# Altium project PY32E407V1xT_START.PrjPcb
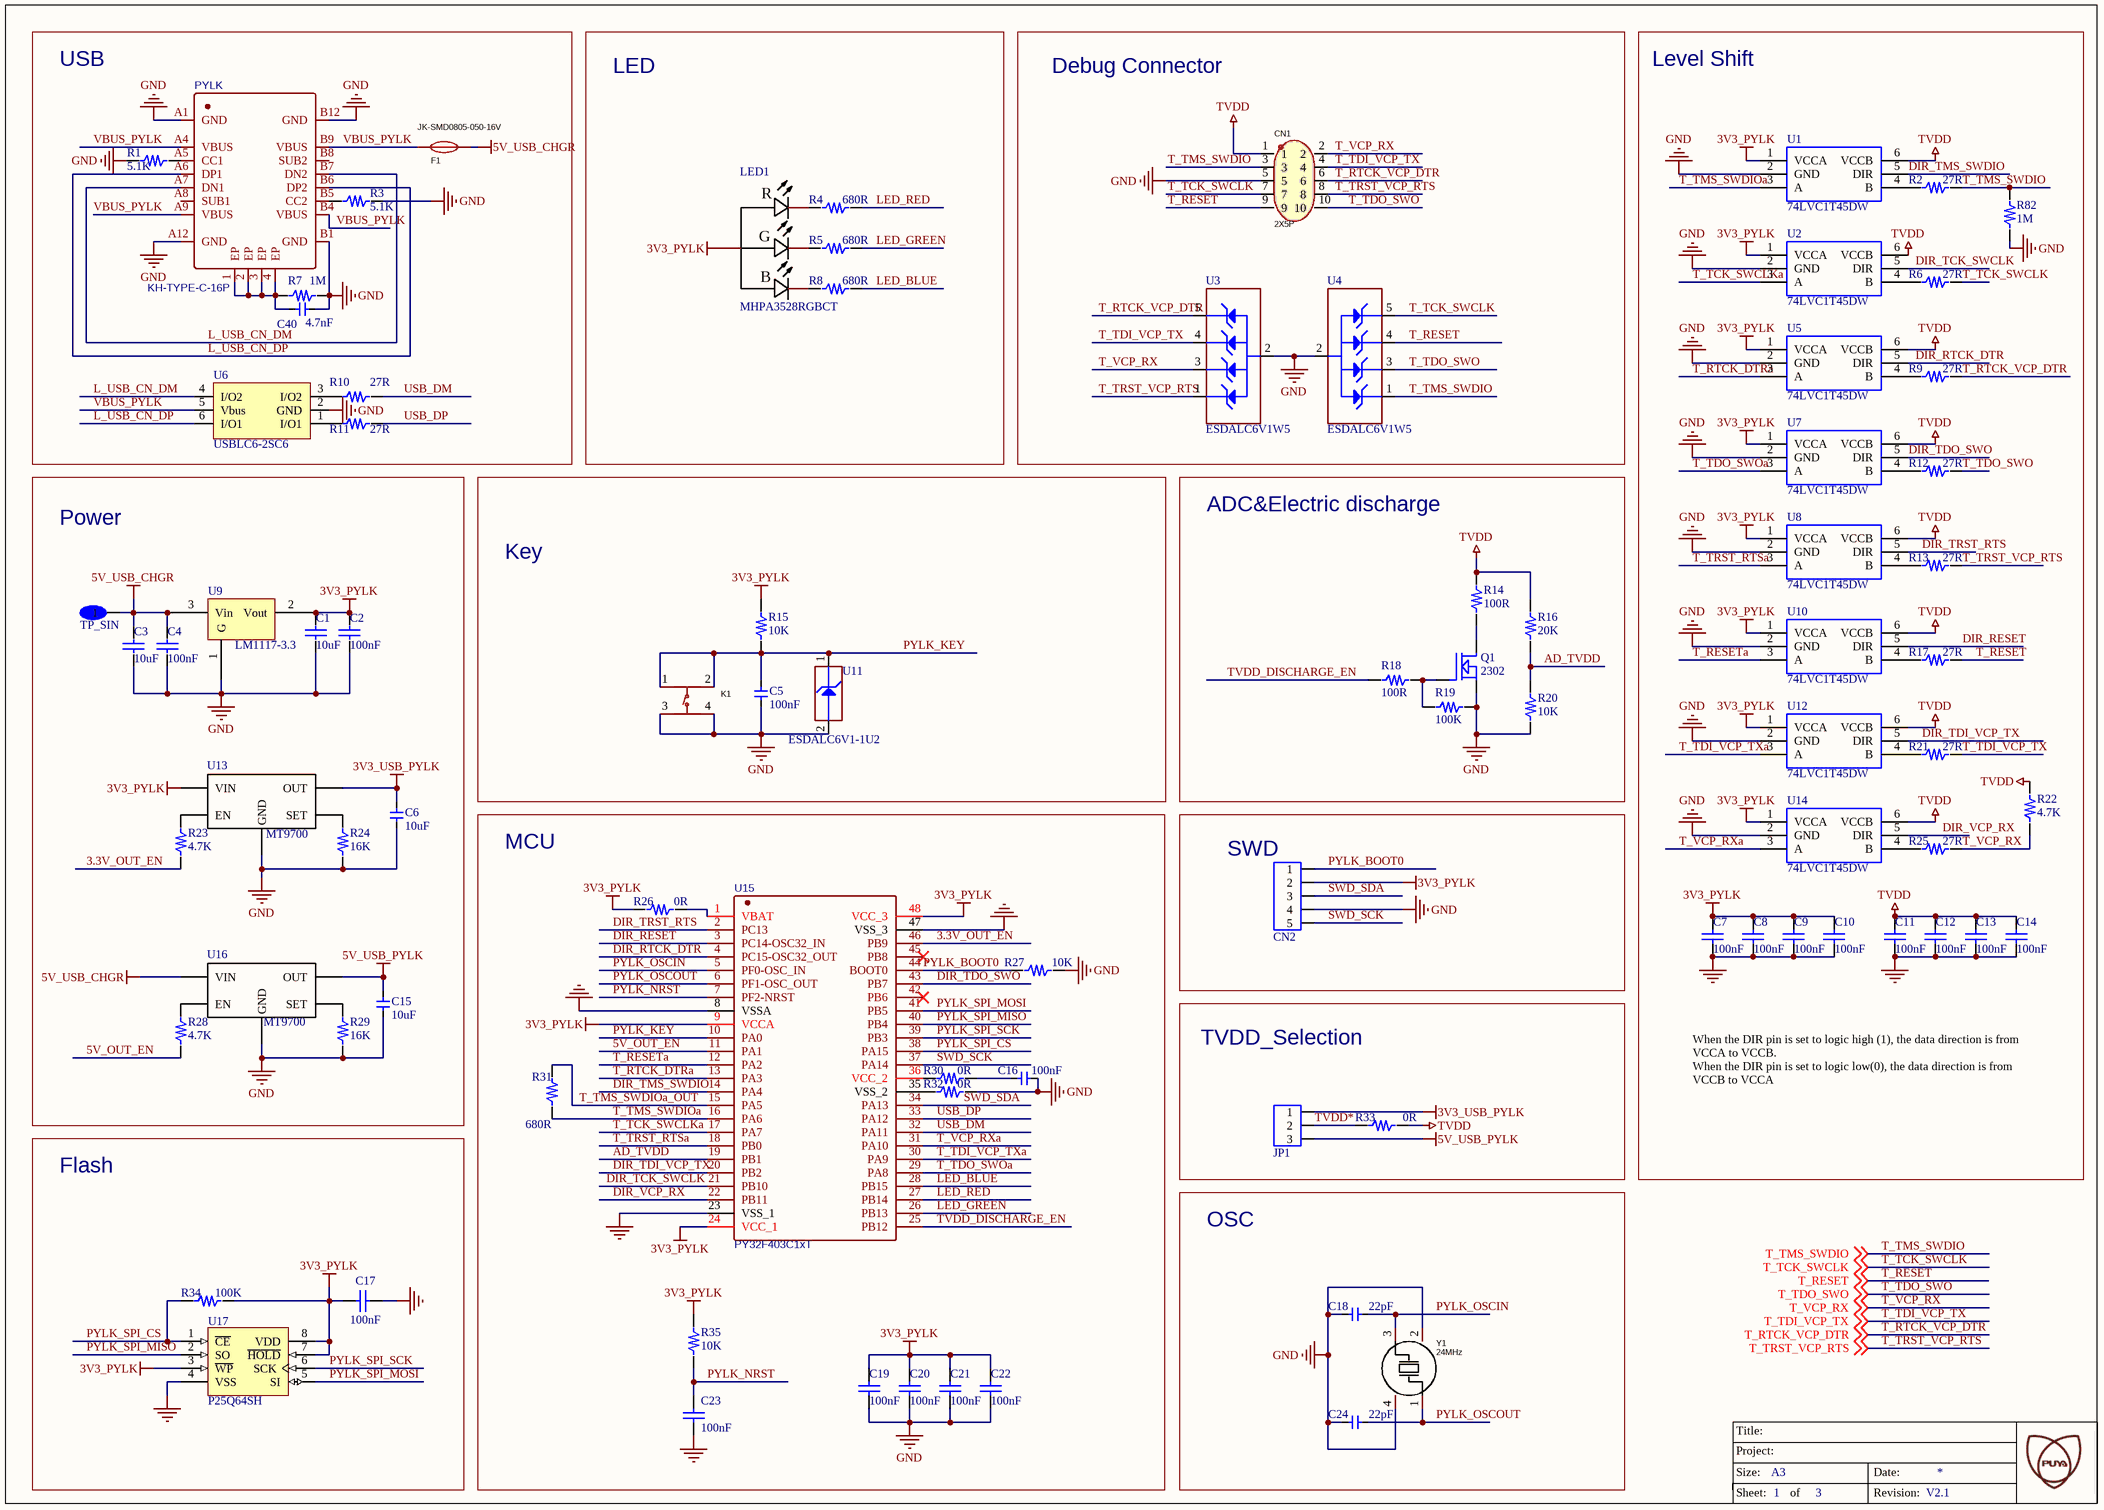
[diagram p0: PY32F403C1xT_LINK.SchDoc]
3 sheets, 210 parts. Net scope: global (net labels, ports and power ports of the same name join across sheets).
Board file: PY32E407V1xT_START.PcbDoc
Sheets:
  PY32F403C1xT_LINK.SchDoc
  PY32E407V1xT_START.SchDoc
  PY32E407V1xT_USB.SchDoc

## Sheet PY32F403C1xT_LINK.SchDoc: =DocumentName
size A3; Revision: V2.1; SheetNumber: 1; SheetTotal: 3; Project: PY32E407V1xT_START.PrjPcb

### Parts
5V_USB_CHGR  TP_SIN  [TP_SIN]
C1  10uF  [C0805]
C2  100nF  [C0603]
C3  10uF  [C0805]
C4  100nF  [C0603]
C5  100nF  [C0603]
C6  10uF  [C0805]
C7  100nF  [C0603]
C8  100nF  [C0603]
C9  100nF  [C0603]
C10  100nF  [C0603]
C11  100nF  [C0603]
C12  100nF  [C0603]
C13  100nF  [C0603]
C14  100nF  [C0603]
C15  10uF  [C0805]
C16  100nF  [C0603]
C17  100nF  [C0603]
C18  22pF  [C0603]
C19  100nF  [C0603]
C20  100nF  [C0603]
C21  100nF  [C0603]
C22  100nF  [C0603]
C23  100nF  [C0603]
C24  22pF  [C0603]
C40  4.7nF  [C0603]
CN1  2X5P  [HDR2X5]
CN2  CON5  [CON5]  (value not drawn)
F1  JK-SMD0805-050-16V  [F0805]
JP1  CON3  [CON3]  (value not drawn)
K1  TS-KG02S  [Switch]  (value not drawn)
LED1  MHPA3528RGBCT  [LED-ARRAY-SMD_4P-L3.5-W2.8-TL]
PYLK  KH-TYPE-C-16P  [USB-C-SMD_KH-TYPE-C-16P]
Q1  2302  [SOT23]
R1  5.1K  [R0603]
R2  27R  [R0603]
R3  5.1K  [R0603]
R4  680R  [R0603]
R5  680R  [R0603]
R6  27R  [R0603]
R7  1M  [R0603]
R8  680R  [R0603]
R9  27R  [R0603]
R10  27R  [R0603]
R11  27R  [R0603]
R12  27R  [R0603]
R13  27R  [R0603]
R14  100R  [R0805]
R15  10K  [R0603]
R16  20K  [R0603]
R17  27R  [R0603]
R18  100R  [R0603]
R19  100K  [R0603]
R20  10K  [R0603]
R21  27R  [R0603]
R22  4.7K  [R0603]
R23  4.7K  [R0603]
R24  16K  [R0603]
R25  27R  [R0603]
R26  0R  [JP2_SMD]
R27  10K  [R0603]
R28  4.7K  [R0603]
R29  16K  [R0603]
R30  0R  [JP2_SMD]
R31  680R  [R0603]
R32  0R  [JP2_SMD]
R33  0R  [JP2_SMD]
R34  100K  [R0603]
R35  10K  [R0603]
R82  1M  [R0603]
U1  74LVC1T45DW  [SOT363]
U2  74LVC1T45DW  [SOT363]
U3  value ESDALC6V1W5  [ESD_SOT323-5L]  (hidden comment: ESD_6V1)
U4  value ESDALC6V1W5  [ESD_SOT323-5L]  (hidden comment: ESD_6V1)
U5  74LVC1T45DW  [SOT363]
U6  USBLC6-2SC6  [SOT23-6]
U7  74LVC1T45DW  [SOT363]
U8  74LVC1T45DW  [SOT363]
U9  LM1117-3.3  [LM1117-3.3]
U10  74LVC1T45DW  [SOT363]
U11  value ESDALC6V1-1U2  [ESD_ST0201]  (hidden comment: ESD-TRANSIL)
U12  74LVC1T45DW  [SOT363]
U13  MT9700  [SOT23-5]
U14  74LVC1T45DW  [SOT363]
U15  PY32F403C1xT  [LQFP-48_L7.0-W7.0-P0.50-LS9.0-BL]
U16  MT9700  [SOT23-5]
U17  P25Q64SH  [SOP-8P]
Y1  24MHz  [CRYSTAL-SMD_4P-L3.2-W2.5-BL]

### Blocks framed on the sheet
USB: C40 F1 PYLK R1 R3 R7 R10 R11 U6
LED: LED1 R4 R5 R8
Debug Connector: CN1 U3 U4
Level Shift: C7-C14 R2 R6 R9 R12 R13 R17 R21 R22 R25 R82 U1 U2 U5 U7 U8 U10 U12 U14
Power: 5V_USB_CHGR C1-C4 C6 C15 R23 R24 R28 R29 U9 U13 U16
Key: C5 K1 R15 U11
ADC&Electric discharge: Q1 R14 R16 R18-R20
MCU: C16 C19-C23 R26 R27 R30-R32 R35 U15
SWD: CN2
TVDD_Selection: JP1 R33
Flash: C17 R34 U17
OSC: C18 C24 Y1

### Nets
3V3_PYLK: C1.2 C2.2 C7.2 C8.2 C9.2 C10.2 C17.2 C19.2 C20.2 C21.2 C22.2 CN2.2 LED1.1(-) R15.2 R26.1 R34.2 R35.2 U1.1(VCCA) U2.1(VCCA) U5.1(VCCA) U7.1(VCCA) U8.1(VCCA) U9.2(Vout) U10.1(VCCA) U12.1(VCCA) U13.5(VIN) U14.1(VCCA) U15.9(VCCA) U15.24(VCC_1) U15.48(VCC_3) U17.3(~{WP}) U17.7(~{HOLD}) U17.8(VDD)
3V3_USB_PYLK: C6.2 JP1.1 U13.1(OUT)
5V_USB_CHGR: 5V_USB_CHGR.1 C3.2 C4.2 F1.2 U9.3(Vin) U16.5(VIN)
5V_USB_PYLK: C15.2 JP1.3 U16.1(OUT)
GND: C1.1 C2.1 C3.1 C4.1 C5.1 C6.1 C7.1 C8.1 C9.1 C10.1 C11.1 C12.1 C13.1 C14.1 C15.1 C16.1 C17.1 C18.1 C19.1 C20.1 C21.1 C22.1 C23.1 C24.1 C40.1 CN1.5 CN2.4 K1.3 K1.4 PYLK.A1(GND) PYLK.A12(GND) PYLK.B1(GND) PYLK.B12(GND) Q1.2(S) R1.1 R3.2 R7.2 R19.1 R20.1 R24.1 R27.2 R29.1 R32.2 R82.1 U1.2(GND) U2.2(GND) U3.2(GND) U4.2(GND) U5.2(GND) U6.2(GND) U7.2(GND) U8.2(GND) U9.1(G) U10.2(GND) U11.2(GND) U12.2(GND) U13.2(GND) U14.2(GND) U15.8(VSSA) U15.23(VSS_1) U15.47(VSS_3) U16.2(GND) U17.4(VSS) Y1.2(GND) Y1.4(GND)
TVDD: C11.2 C12.2 C13.2 C14.2 CN1.1 R14.2 R16.2 R22.2 R33.2 U1.6(VCCB) U2.6(VCCB) U5.6(VCCB) U7.6(VCCB) U8.6(VCCB) U10.6(VCCB) U12.6(VCCB) U14.6(VCCB)
3.3V_OUT_EN: R23.1 U15.46(PB9)
5V_OUT_EN: R28.1 U15.11(PA1)
AD_TVDD: R16.1 R20.2 U15.19(PB1)
DIR_RESET: U10.5(DIR) U15.3(PC14-OSC32_IN)
DIR_RTCK_DTR: U5.5(DIR) U15.4(PC15-OSC32_OUT)
DIR_TCK_SWCLK: U2.5(DIR) U15.21(PB10)
DIR_TDI_VCP_TX: U12.5(DIR) U15.20(PB2)
DIR_TDO_SWO: U7.5(DIR) U15.43(PB7)
DIR_TMS_SWDIO: U1.5(DIR) U15.14(PA4)
DIR_TRST_RTS: U8.5(DIR) U15.2(PC13)
DIR_VCP_RX: U14.5(DIR) U15.22(PB11)
L_USB_CN_DM: PYLK.A7(DN1) PYLK.B7(DN2) U6.4(I/O2)
L_USB_CN_DP: PYLK.A6(DP1) PYLK.B6(DP2) U6.6(I/O1)
LED_BLUE: R8.2 U15.28(PB15)
LED_GREEN: R5.2 U15.26(PB13)
LED_RED: R4.2 U15.27(PB14)
PYLK_BOOT0: CN2.1 R27.1 U15.44(BOOT0)
PYLK_KEY: C5.2 K1.1 K1.2 R15.1 U11.1(IO1) U15.10(PA0)
PYLK_NRST: C23.2 R35.1 U15.7(PF2-NRST)
PYLK_OSCIN: C18.2 U15.5(PF0-OSC_IN) Y1.3(OSC2)
PYLK_OSCOUT: C24.2 U15.6(PF1-OSC_OUT) Y1.1(OSC1)
PYLK_SPI_CS: R34.1 U15.38(PA15) U17.1(~{CE})
PYLK_SPI_MISO: U15.40(PB4) U17.2(SO)
PYLK_SPI_MOSI: U15.41(PB5) U17.5(SI)
PYLK_SPI_SCK: U15.39(PB3) U17.6(SCK)
SWD_SCK: CN2.5 U15.37(PA14)
SWD_SDA: CN2.3 U15.34(PA13)
T_RESET: CN1.9 R17.2 U4.4(IO3) ; off-sheet T_RESET
T_RESETa: U10.3(A) U15.12(PA2)
T_RTCK_DTRa: U5.3(A) U15.13(PA3)
T_RTCK_VCP_DTR: CN1.6 R9.2 U3.5(IO4) ; off-sheet T_RTCK_VCP_DTR
T_TCK_SWCLK: CN1.7 R6.2 U4.5(IO4) ; off-sheet T_TCK_SWCLK
T_TCK_SWCLKa: U2.3(A) U15.17(PA7)
T_TDI_VCP_TX: CN1.4 R21.2 U3.4(IO3) ; off-sheet T_TDI_VCP_TX
T_TDI_VCP_TXa: U12.3(A) U15.30(PA9)
T_TDO_SWO: CN1.10 R12.2 U4.3(IO2) ; off-sheet T_TDO_SWO
T_TDO_SWOa: U7.3(A) U15.29(PA8)
T_TMS_SWDIO: CN1.3 R2.2 R82.2 U4.1(IO1) ; off-sheet T_TMS_SWDIO
T_TMS_SWDIOa: R31.1 U1.3(A) U15.16(PA6)
T_TMS_SWDIOa_OUT: R31.2 U15.15(PA5)
T_TRST_RTSa: U8.3(A) U15.18(PB0)
T_TRST_VCP_RTS: CN1.8 R13.2 U3.1(IO1) ; off-sheet T_TRST_VCP_RTS
T_VCP_RX: CN1.2 R22.1 R25.2 U3.3(IO2) ; off-sheet T_VCP_RX
T_VCP_RXa: U14.3(A) U15.31(PA10)
TVDD*: JP1.2 R33.1
TVDD_DISCHARGE_EN: R18.2 U15.25(PB12)
USB_DM: R10.2 U15.32(PA11)
USB_DP: R11.2 U15.33(PA12)
VBUS_PYLK: F1.1 PYLK.A4(VBUS) PYLK.A9(VBUS) PYLK.B4(VBUS) PYLK.B9(VBUS) U6.5(Vbus)
NetC16_2: C16.2 R30.2
NetC40_2: C40.2 PYLK.1(EP) PYLK.2(EP) PYLK.3(EP) PYLK.4(EP) R7.1
NetLED1_2: LED1.2(-) R8.1
NetLED1_3: LED1.3(-) R5.1
NetLED1_4: LED1.4(-) R4.1
NetPYLK_A5: PYLK.A5(CC1) R1.2
NetPYLK_B5: PYLK.B5(CC2) R3.1
NetQ1_1: Q1.1(G) R18.1 R19.2
NetQ1_3: Q1.3(D) R14.1
NetR2_1: R2.1 U1.4(B)
NetR6_1: R6.1 U2.4(B)
NetR9_1: R9.1 U5.4(B)
NetR10_1: R10.1 U6.3(I/O2)
NetR11_1: R11.1 U6.1(I/O1)
NetR12_1: R12.1 U7.4(B)
NetR13_1: R13.1 U8.4(B)
NetR17_1: R17.1 U10.4(B)
NetR21_1: R21.1 U12.4(B)
NetR23_2: R23.2 U13.4(EN)
NetR24_2: R24.2 U13.3(SET)
NetR25_1: R25.1 U14.4(B)
NetR26_2: R26.2 U15.1(VBAT)
NetR28_2: R28.2 U16.4(EN)
NetR29_2: R29.2 U16.3(SET)
NetR30_1: R30.1 U15.36(VCC_2)
NetR32_1: R32.1 U15.35(VSS_2)

Not connected (* = marked no-connect by the designer): PYLK A8(SUB1) B8(SUB2); U15 42(PB6)* 45(PB8)*

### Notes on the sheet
- When the DIR pin is set to logic high (1), the data direction is from VCCA to VCCB.
  When the DIR pin is set to logic low(0), the data direction is from VCCB to VCCA

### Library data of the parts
C1 C3 C6 C15 = C0805: PCB DECAL: 0805
C2 C4 C5 C16 C18 C24 C40 = C0603: PCB DECAL: 0603
C7-C14 C17 C19-C23 = 贴片高压陶瓷电容: Capacitor (Semiconductor SIM Model); 器件封装(外观): 0603; Value: 104
CN1 = 2X5P: Manufacturer: XFCN(兴飞); Symbol: PZ254V-12-10P; Add into BOM: yes; Pitch: 2.54mm; Circluar Pins/Square Pins: 方针
F1 = JK-SMD0805-050-16V: Manufacturer: JK(金科); Add into BOM: yes; Voltage - Max: 6V; Current - Max: 100A; Hold Current: 500mA; Trip Current: 1A; Power Dissipation: 600mW; Resistance - Initial (Ri) (Min): 150mΩ; Resistance - Post Trip (R1) (Max): 850mΩ; Time to Trip(Max): 100ms
K1 = TS-KG02S-AT50F: Manufacturer: HANBO(汉博); Add into BOM: yes; Circuit: 单刀单掷; Actuator Style: 圆形按钮; Operating Force: 250gf; Switch Length: 6mm; Switch Height: 5mm; Strike Gundam: 不带; Contact Current: 50mA; Voltage Rating (DC): 12V; Insulation Resistance: 100MΩ; Actuator/Cap Color: 黑色; Pin Style: 鸥翼型
LED1 = MHPA3528RGBCT: Manufacturer: MEIHUA(美华); Add into BOM: yes
PYLK = KH-TYPE-C-16P: BOM_Manufacturer: Shenzhen Kinghelm Elec; Contributor: LCSC
Q1 = MOSFET N: Value: SI2302
R1-R13 R15-R35 R82 = R0603: PCB DECAL: 0603
R14 = R0805: PCB DECAL: 0805
U3 U4 = ESDALC6V1W5: Dual Transil array for ESD protection; Internal_Part_Number: MCD-00136; Part_Type: Diode; Manufacturer: STMICROELECTRONICS; ECCN_US: EAR99; ECCN_EU: NEC; Provided_By: Subcon; Initial_Board_Reference: MB1262
U6 = USBLC6-2SC6: Function: ESD EMI fliter
U11 = ESD-TRANSIL: ESD protection 6V1; Internal_Part_Number: MCD-00170; Part_Type: Diode; Manufacturer: STMICROELECTRONICS; ECCN_US: EAR99; ECCN_EU: NEC; Provided_By: Subcon; Initial_Board_Reference: MB1274
U15 = PY32F403C1xT: LQFP48; BOM_Manufacturer: PUYA(普冉)
U17 = SST25VF010: Value: SST25VF020B; 器件封装(外观): SOP8
Y1 = ABM8AIG-24.000MHZ-82Z-T: ±20ppm , 12.5pF , T_use: -40°C~125°C; Manufacturer: ABRACON; Add into BOM: yes; External load capacitor: 8pF; Frequency Stability(Full temperature range): ±50ppm; Equivalent Series Resistance (ESR): 50Ω

## Sheet PY32E407V1xT_START.SchDoc: =DocumentName
size A3; Revision: V2.1; SheetNumber: 2; SheetTotal: 3; Project: PY32E407V1xT_START.PrjPcb
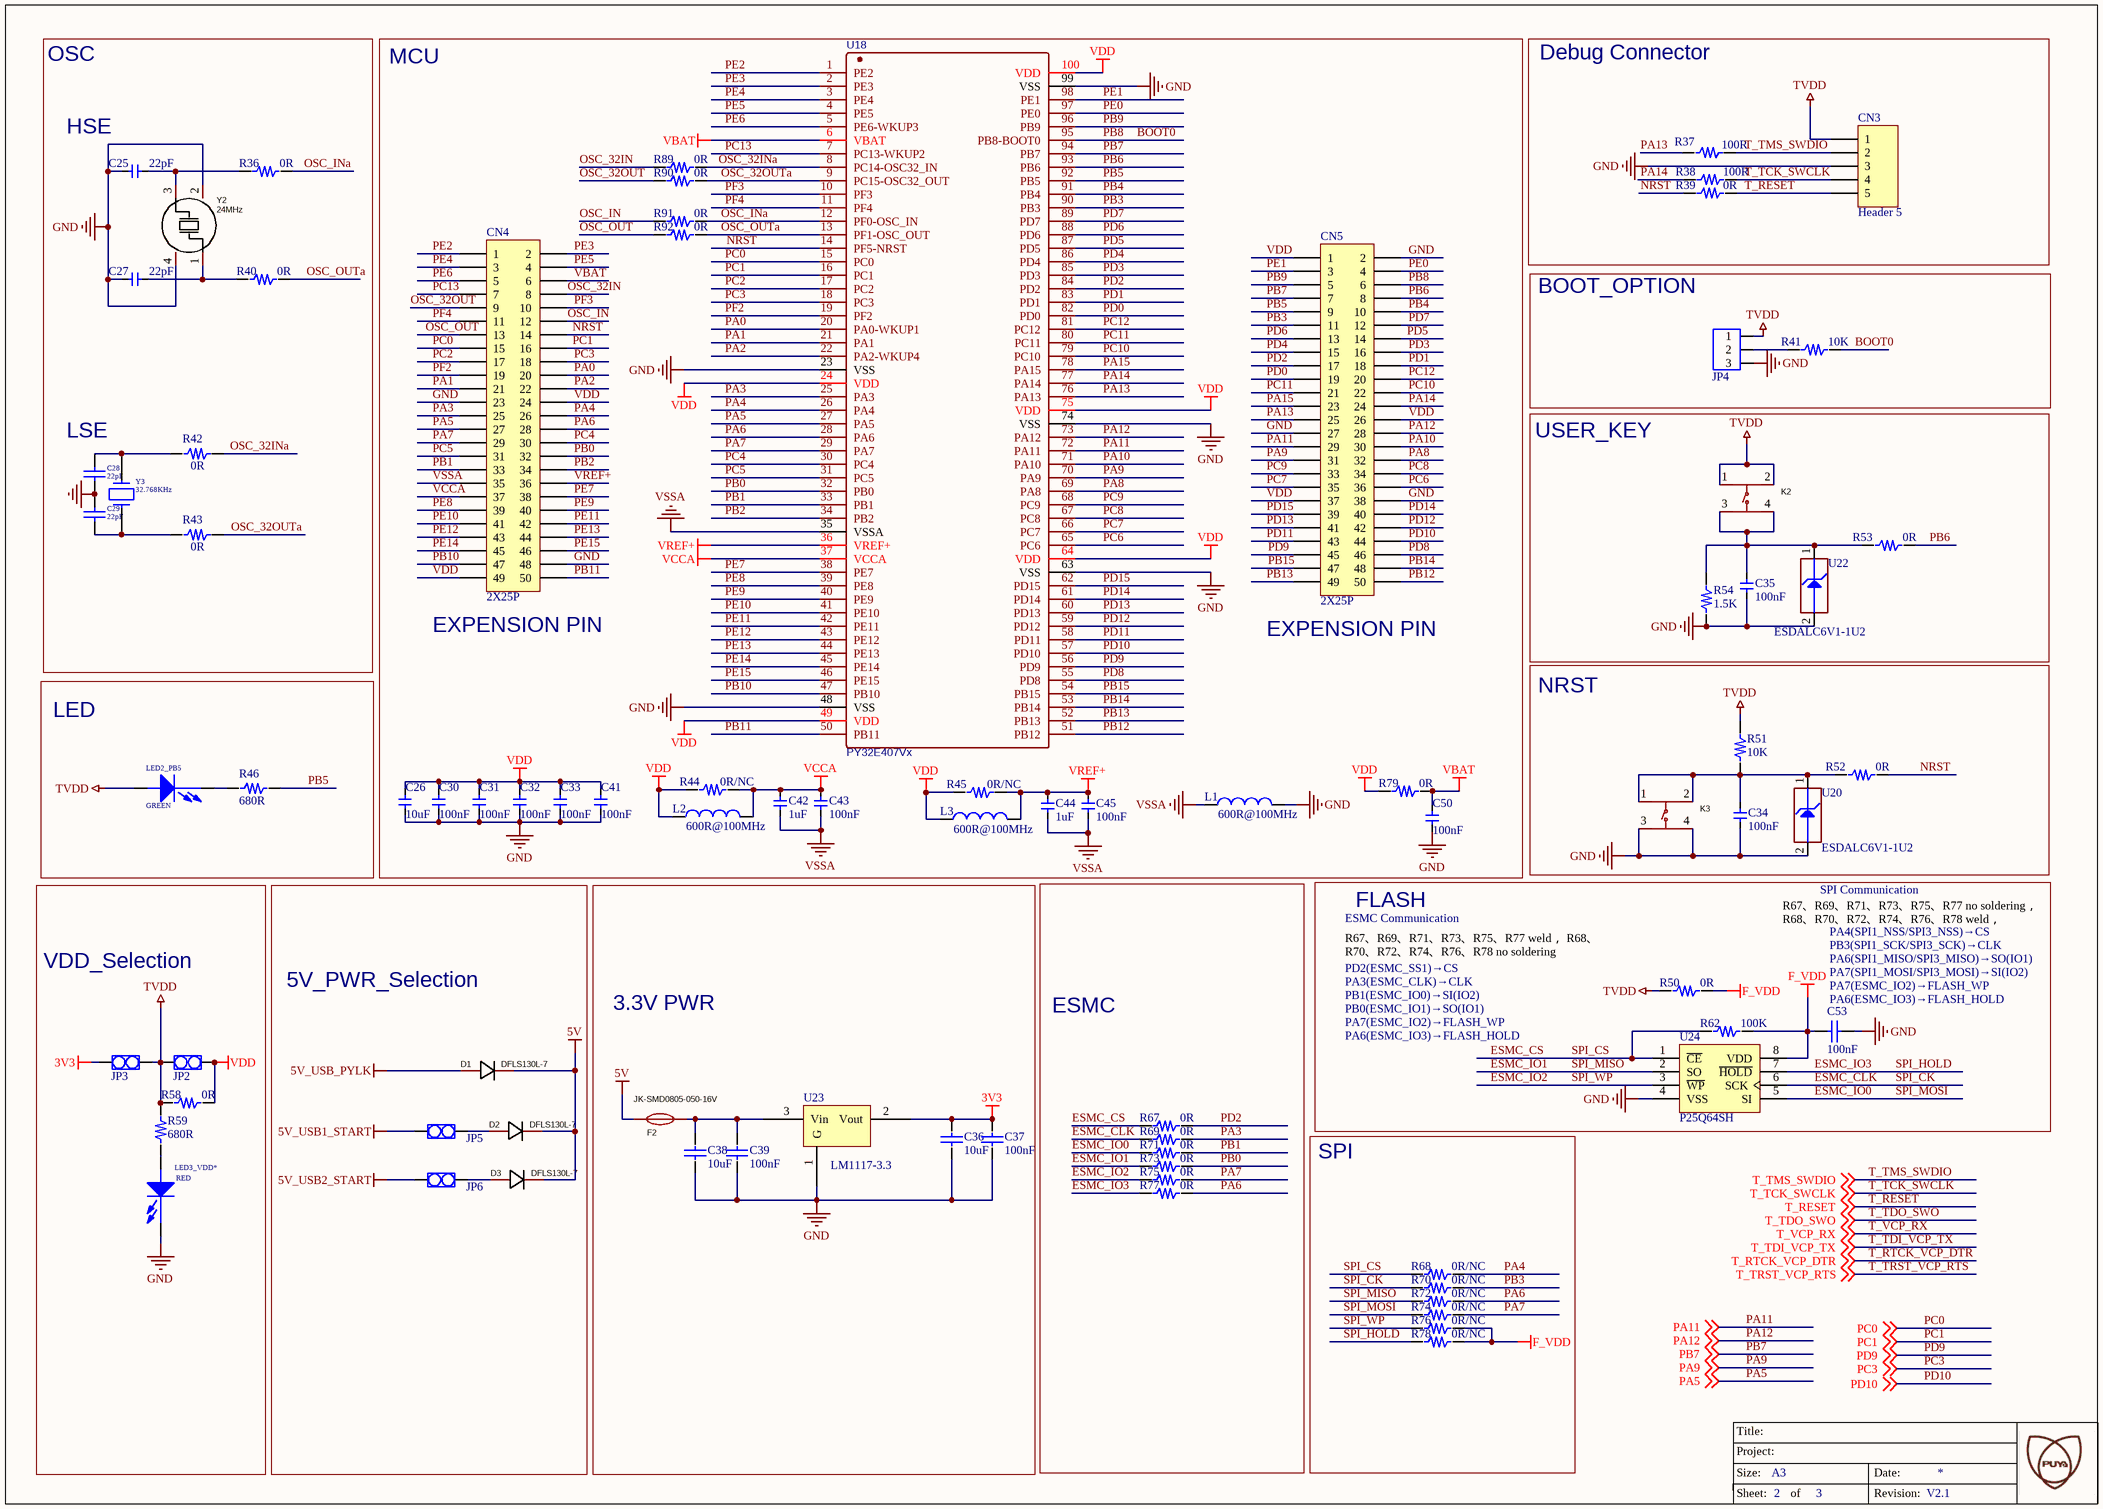
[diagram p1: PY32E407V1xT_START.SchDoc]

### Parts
C25  22pF  [C0603]
C26  10uF  [C0603]
C27  22pF  [C0603]
C28  22pF  [C0603]
C29  22pF  [C0603]
C30  100nF  [C0603]
C31  100nF  [C0603]
C32  100nF  [C0603]
C33  100nF  [C0603]
C34  100nF  [C0603]
C35  100nF  [C0603]
C36  10uF  [C0805]
C37  100nF  [C0603]
C38  10uF  [C0805]
C39  100nF  [C0603]
C41  100nF  [C0603]
C42  1uF  [C0603]
C43  100nF  [C0603]
C44  1uF  [C0603]
C45  100nF  [C0603]
C50  100nF  [C0603]
C53  100nF  [C0603]
CN3  Header 5  [HDR1X5]
CN4  2X25P  [HDR2X25]
CN5  2X25P  [HDR2X25]
D1  DFLS130L-7  [POWERDI-123_L2.8-W1.8-LS3.7-RD]
D2  DFLS130L-7  [POWERDI-123_L2.8-W1.8-LS3.7-RD]
D3  DFLS130L-7  [POWERDI-123_L2.8-W1.8-LS3.7-RD]
F2  JK-SMD0805-050-16V  [F0805]
JP2  CON2  [CON2]  (value not drawn)
JP3  CON2  [CON2]  (value not drawn)
JP4  CON3  [CON3]  (value not drawn)
JP5  CON2  [CON2]  (value not drawn)
JP6  CON2  [CON2]  (value not drawn)
K2  TS-KG02S  [Switch]  (value not drawn)
K3  TS-KG02S  [Switch]  (value not drawn)
L1  value 600R@100MHz  [L0603]  (hidden comment: BEAD)
L2  value 600R@100MHz  [L0603]  (hidden comment: BEAD)
L3  value 600R@100MHz  [L0603]  (hidden comment: BEAD)
LED2_PB5  GREEN  [0603_LED]
LED3_VDD*  RED  [0603_LED]
R36  0R  [JP2_SMD]
R37  100R  [JP2_SMD]
R38  100R  [JP2_SMD]
R39  0R  [JP2_SMD]
R40  0R  [JP2_SMD]
R41  10K  [R0603]
R42  0R  [JP2_SMD]
R43  0R  [JP2_SMD]
R44  0R/NC  [JP2_SMD]
R45  0R/NC  [JP2_SMD]
R46  680R  [R0603]
R50  0R  [JP2_SMD]
R51  10K  [R0603]
R52  0R  [JP2_SMD]
R53  0R  [JP2_SMD]
R54  1.5K  [R0603]
R58  0R  [JP2_SMD]
R59  680R  [R0603]
R62  100K  [R0603]
R67  0R  [R0603]
R68  0R/NC  [R0603]
R69  0R  [R0603]
R70  0R/NC  [R0603]
R71  0R  [R0603]
R72  0R/NC  [R0603]
R73  0R  [R0603]
R74  0R/NC  [R0603]
R75  0R  [R0603]
R76  0R/NC  [R0603]
R77  0R  [R0603]
R78  0R/NC  [R0603]
R79  0R  [R0603]
R89  0R  [JP2_SMD]
R90  0R  [JP2_SMD]
R91  0R  [JP2_SMD]
R92  0R  [JP2_SMD]
U18  PY32E407Vx  [LQFP-100_L14.0-W14.0-P0.50-LS16.0-BL]
U20  value ESDALC6V1-1U2  [ESD_ST0201]  (hidden comment: ESD-TRANSIL)
U22  value ESDALC6V1-1U2  [ESD_ST0201]  (hidden comment: ESD-TRANSIL)
U23  LM1117-3.3  [LM1117-3.3]
U24  P25Q64SH  [SOP-8P]
Y2  24MHz  [CRYSTAL-SMD_4P-L3.2-W2.5-BL]
Y3  32.768KHz  [CRYSTAL-SMD_L3.2-W1.5-1]

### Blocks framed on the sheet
Debug Connector: CN3 R37-R39
BOOT_OPTION: JP4 R41
USER_KEY: C35 K2 R53 R54 U22
NRST: C34 K3 R51 R52 U20
LED: LED2_PB5 R46
FLASH: C53 R50 R62 U24
VDD_Selection: JP2 JP3 LED3_VDD* R58 R59
5V_PWR_Selection: D1-D3 JP5 JP6
3.3V PWR: C36-C39 F2 U23
ESMC: R67 R69 R71 R73 R75 R77
SPI: R68 R70 R72 R74 R76 R78

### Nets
3V3: C36.2 C37.2 JP3.2 U23.2(Vout)
5V: D1.1 D2.1 D3.1 F2.1
5V_USB1_START: JP5.1
5V_USB2_START: JP6.1
5V_USB_PYLK: D1.2
F_VDD: C53.2 R50.2 R62.2 R76.2 R78.2 U24.8(VDD)
GND: C25.1 C26.1 C27.1 C28.2 C29.1 C30.1 C31.1 C32.1 C33.1 C34.1 C35.1 C36.1 C37.1 C38.1 C39.1 C41.1 C50.1 C53.1 CN3.3 CN4.23 CN4.48 CN5.2 CN5.27 CN5.38 JP4.3 K3.3 K3.4 L1.2 LED3_VDD*.2(CATHODE) R54.1 U18.23(VSS) U18.48(VSS) U18.63(VSS) U18.74(VSS) U18.99(VSS) U20.2(GND) U22.2(GND) U23.1(G) U24.4(VSS) Y2.2(GND) Y2.4(GND)
TVDD: CN3.1 JP2.1 JP3.1 JP4.1 K2.1 K2.2 LED2_PB5.1(ANODE) R50.1 R51.1 R58.1 R59.2
VBAT: C50.2 CN4.6 R79.2 U18.6(VBAT)
VCCA: C42.2 C43.2 CN4.37 L2.2 R44.2 U18.37(VCCA)
VDD: C26.2 C30.2 C31.2 C32.2 C33.2 C41.2 CN4.24 CN4.49 CN5.1 CN5.26 CN5.37 JP2.2 L2.1 L3.1 R44.1 R45.1 R58.2 R79.1 U18.24(VDD) U18.49(VDD) U18.64(VDD) U18.75(VDD) U18.100(VDD)
VREF+: C44.2 C45.2 CN4.36 L3.2 R45.2 U18.36(VREF+)
VSSA: C42.1 C43.1 C44.1 C45.1 CN4.35 L1.1 U18.35(VSSA)
BOOT0: CN5.6 R41.2 U18.95(PB8-BOOT0)  [also labelled PB8]
ESMC_CLK: R69.1 R70.1 U24.6(SCK)  [also labelled SPI_CK]
ESMC_CS: R62.1 R67.1 R68.1 U24.1(~{CE})  [also labelled SPI_CS]
ESMC_IO0: R71.1 R74.1 U24.5(SI)  [also labelled SPI_MOSI]
ESMC_IO1: R72.1 R73.1 U24.2(SO)  [also labelled SPI_MISO]
ESMC_IO2: R75.1 R76.1 U24.3(~{WP})  [also labelled SPI_WP]
ESMC_IO3: R77.1 R78.1 U24.7(~{HOLD})  [also labelled SPI_HOLD]
NRST: CN4.14 R39.2 R52.2 U18.14(PF5-NRST)
OSC_32IN: CN4.8 R89.2
OSC_32INa: R42.1 R89.1 U18.8(PC14-OSC32_IN)
OSC_32OUT: CN4.9 R90.2
OSC_32OUTa: R43.1 R90.1 U18.9(PC15-OSC32_OUT)
OSC_IN: CN4.12 R91.2
OSC_INa: R36.2 R91.1 U18.12(PF0-OSC_IN)
OSC_OUT: CN4.13 R92.2
OSC_OUTa: R40.2 R92.1 U18.13(PF1-OSC_OUT)
PA0: CN4.20 U18.20(PA0-WKUP1)
PA1: CN4.21 U18.21(PA1)
PA2: CN4.22 U18.22(PA2-WKUP4)
PA3: CN4.25 R69.2 U18.25(PA3)
PA4: CN4.26 R68.2 U18.26(PA4)
PA5: CN4.27 U18.27(PA5) ; off-sheet PA5
PA6: CN4.28 R72.2 R77.2 U18.28(PA6)
PA7: CN4.29 R74.2 R75.2 U18.29(PA7)
PA8: CN5.32 U18.69(PA8)
PA9: CN5.31 U18.70(PA9) ; off-sheet PA9
PA10: CN5.30 U18.71(PA10)
PA11: CN5.29 U18.72(PA11) ; off-sheet PA11
PA12: CN5.28 U18.73(PA12) ; off-sheet PA12
PA13: CN5.25 R37.2 U18.76(PA13)
PA14: CN5.24 R38.2 U18.77(PA14)
PA15: CN5.23 U18.78(PA15)
PB0: CN4.32 R73.2 U18.32(PB0)
PB1: CN4.33 R71.2 U18.33(PB1)
PB2: CN4.34 U18.34(PB2)
PB3: CN5.11 R70.2 U18.90(PB3)
PB4: CN5.10 U18.91(PB4)
PB5: CN5.9 R46.2 U18.92(PB5)
PB6: CN5.8 R53.2 U18.93(PB6)
PB7: CN5.7 U18.94(PB7) ; off-sheet PB7
PB9: CN5.5 U18.96(PB9)
PB10: CN4.47 U18.47(PB10)
PB11: CN4.50 U18.50(PB11)
PB12: CN5.50 U18.51(PB12)
PB13: CN5.49 U18.52(PB13)
PB14: CN5.48 U18.53(PB14)
PB15: CN5.47 U18.54(PB15)
PC0: CN4.15 U18.15(PC0) ; off-sheet PC0
PC1: CN4.16 U18.16(PC1) ; off-sheet PC1
PC2: CN4.17 U18.17(PC2)
PC3: CN4.18 U18.18(PC3) ; off-sheet PC3
PC4: CN4.30 U18.30(PC4)
PC5: CN4.31 U18.31(PC5)
PC6: CN5.36 U18.65(PC6)
PC7: CN5.35 U18.66(PC7)
PC8: CN5.34 U18.67(PC8)
PC9: CN5.33 U18.68(PC9)
PC10: CN5.22 U18.79(PC10)
PC11: CN5.21 U18.80(PC11)
PC12: CN5.20 U18.81(PC12)
PC13: CN4.7 U18.7(PC13-WKUP2)
PD0: CN5.19 U18.82(PD0)
PD1: CN5.18 U18.83(PD1)
PD2: CN5.17 R67.2 U18.84(PD2)
PD3: CN5.16 U18.85(PD3)
PD4: CN5.15 U18.86(PD4)
PD5: CN5.14 U18.87(PD5)
PD6: CN5.13 U18.88(PD6)
PD7: CN5.12 U18.89(PD7)
PD8: CN5.46 U18.55(PD8)
PD9: CN5.45 U18.56(PD9) ; off-sheet PD9
PD10: CN5.44 U18.57(PD10) ; off-sheet PD10
PD11: CN5.43 U18.58(PD11)
PD12: CN5.42 U18.59(PD12)
PD13: CN5.41 U18.60(PD13)
PD14: CN5.40 U18.61(PD14)
PD15: CN5.39 U18.62(PD15)
PE0: CN5.4 U18.97(PE0)
PE1: CN5.3 U18.98(PE1)
PE2: CN4.1 U18.1(PE2)
PE3: CN4.2 U18.2(PE3)
PE4: CN4.3 U18.3(PE4)
PE5: CN4.4 U18.4(PE5)
PE6: CN4.5 U18.5(PE6-WKUP3)
PE7: CN4.38 U18.38(PE7)
PE8: CN4.39 U18.39(PE8)
PE9: CN4.40 U18.40(PE9)
PE10: CN4.41 U18.41(PE10)
PE11: CN4.42 U18.42(PE11)
PE12: CN4.43 U18.43(PE12)
PE13: CN4.44 U18.44(PE13)
PE14: CN4.45 U18.45(PE14)
PE15: CN4.46 U18.46(PE15)
PF2: CN4.19 U18.19(PF2)
PF3: CN4.10 U18.10(PF3)
PF4: CN4.11 U18.11(PF4)
T_RESET: CN3.5 R39.1 ; off-sheet T_RESET
T_TCK_SWCLK: CN3.4 R38.1 ; off-sheet T_TCK_SWCLK
T_TMS_SWDIO: CN3.2 R37.1 ; off-sheet T_TMS_SWDIO
NetC25_2: C25.2 R36.1 Y2.3(OSC2)
NetC27_2: C27.2 R40.1 Y2.1(OSC1)
NetC28_1: C28.1 R42.2 Y3.2
NetC29_2: C29.2 R43.2 Y3.1
NetC34_2: C34.2 K3.1 K3.2 R51.2 R52.1 U20.1(IO1)
NetC35_2: C35.2 K2.3 K2.4 R53.1 R54.2 U22.1(IO1)
NetC38_2: C38.2 C39.2 F2.2 U23.3(Vin)
NetD2_2: D2.2 JP5.2
NetD3_2: D3.2 JP6.2
NetJP4_2: JP4.2 R41.1
NetLED2_PB5_2: LED2_PB5.2(CATHODE) R46.1
NetLED3_VDD*_1: LED3_VDD*.1(ANODE) R59.1

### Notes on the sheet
- OSC
- MCU
- (near C25) HSE
- (near C28) LSE
- (near CN4) EXPENSION PIN
- (near CN5) EXPENSION PIN
- ESMC Communication
- R67、R69、R71、R73、R75、R77 no soldering， R68、R70、R72、R74、R76、R78 weld，
- (near U20) SPI Communication
- PA3(ESMC_CLK)→CLK
- PD2(ESMC_SS1)→CS
- R67、R69、R71、R73、R75、R77 weld， R68、R70、R72、R74、R76、R78 no soldering
- PB3(SPI1_SCK/SPI3_SCK)→CLK
- PA6(SPI1_MISO/SPI3_MISO)→SO(IO1)
- (near C53) PA7(SPI1_MOSI/SPI3_MOSI)→SI(IO2)
- PA4(SPI1_NSS/SPI3_NSS)→CS
- (near C53) PA7(ESMC_IO2)→FLASH_WP
- PB0(ESMC_IO1)→SO(IO1)
- PB1(ESMC_IO0)→SI(IO2)
- PA7(ESMC_IO2)→FLASH_WP
- PA6(ESMC_IO3)→FLASH_HOLD
- (near C53) PA6(ESMC_IO3)→FLASH_HOLD

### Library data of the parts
C25-C27 C30-C35 C37 C39 C41 C43 C45 C50 = C0603: PCB DECAL: 0603
C28 C29 = Cap: Capacitor
C36 C38 C42 C44 = C0805: PCB DECAL: 0805
C53 = 贴片高压陶瓷电容: as C7 on sheet PY32F403C1xT_LINK
CN3 = Header 5: Header, 5-Pin
CN4 CN5 = Header 25X2: Header, 25-Pin, Dual row
D1-D3 = DFLS130L-7: Manufacturer: DIODES(美台); Add into BOM: yes; Forward Voltage (Vf@If): 310mV@1A; Reverse Voltage (Vr): 30V; Average Rectified Current (Io): 1A
F2 = JK-SMD0805-050-16V: as F1 on sheet PY32F403C1xT_LINK
JP2 JP3 JP5 JP6 = CON2_DIP
K2 K3 = TS-KG02S-AT50F: as K1 on sheet PY32F403C1xT_LINK
L1-L3 = BEAD: SMD Chip ferrite bead, 600R@100MHz +/-25%, 350mA, 500mohm DC, 0603, T=0.8mm; Internal_Part_Number: MCD-00047; Part_Type: Inductor; Manufacturer_Part_Number: FCM1608KF-601T03; Manufacturer: TAI-TECH; Provided_By: SUBCO
LED2_PB5 LED3_VDD* = PDI-E803_Dup1
R36-R46 R50-R54 R58 R59 R62 R67-R79 R89-R92 = R0603: PCB DECAL: 0603
U18 = PY32E407Vx: LQFP100; BOM_Manufacturer: PUYA(普冉)
U20 U22 = ESD-TRANSIL: as U11 on sheet PY32F403C1xT_LINK
U24 = SST25VF010: Value: SST25VF020B; 器件封装(外观): SOP8
Y2 = ABM8AIG-24.000MHZ-82Z-T: as Y1 on sheet PY32F403C1xT_LINK
Y3 = CRYSTAL_1: Crystal; Value: X503225MSB2GI

## Sheet PY32E407V1xT_USB.SchDoc: =DocumentName
size A3; Revision: V2.1; SheetNumber: 3; SheetTotal: 3; Project: PY32E407V1xT_START.PrjPcb
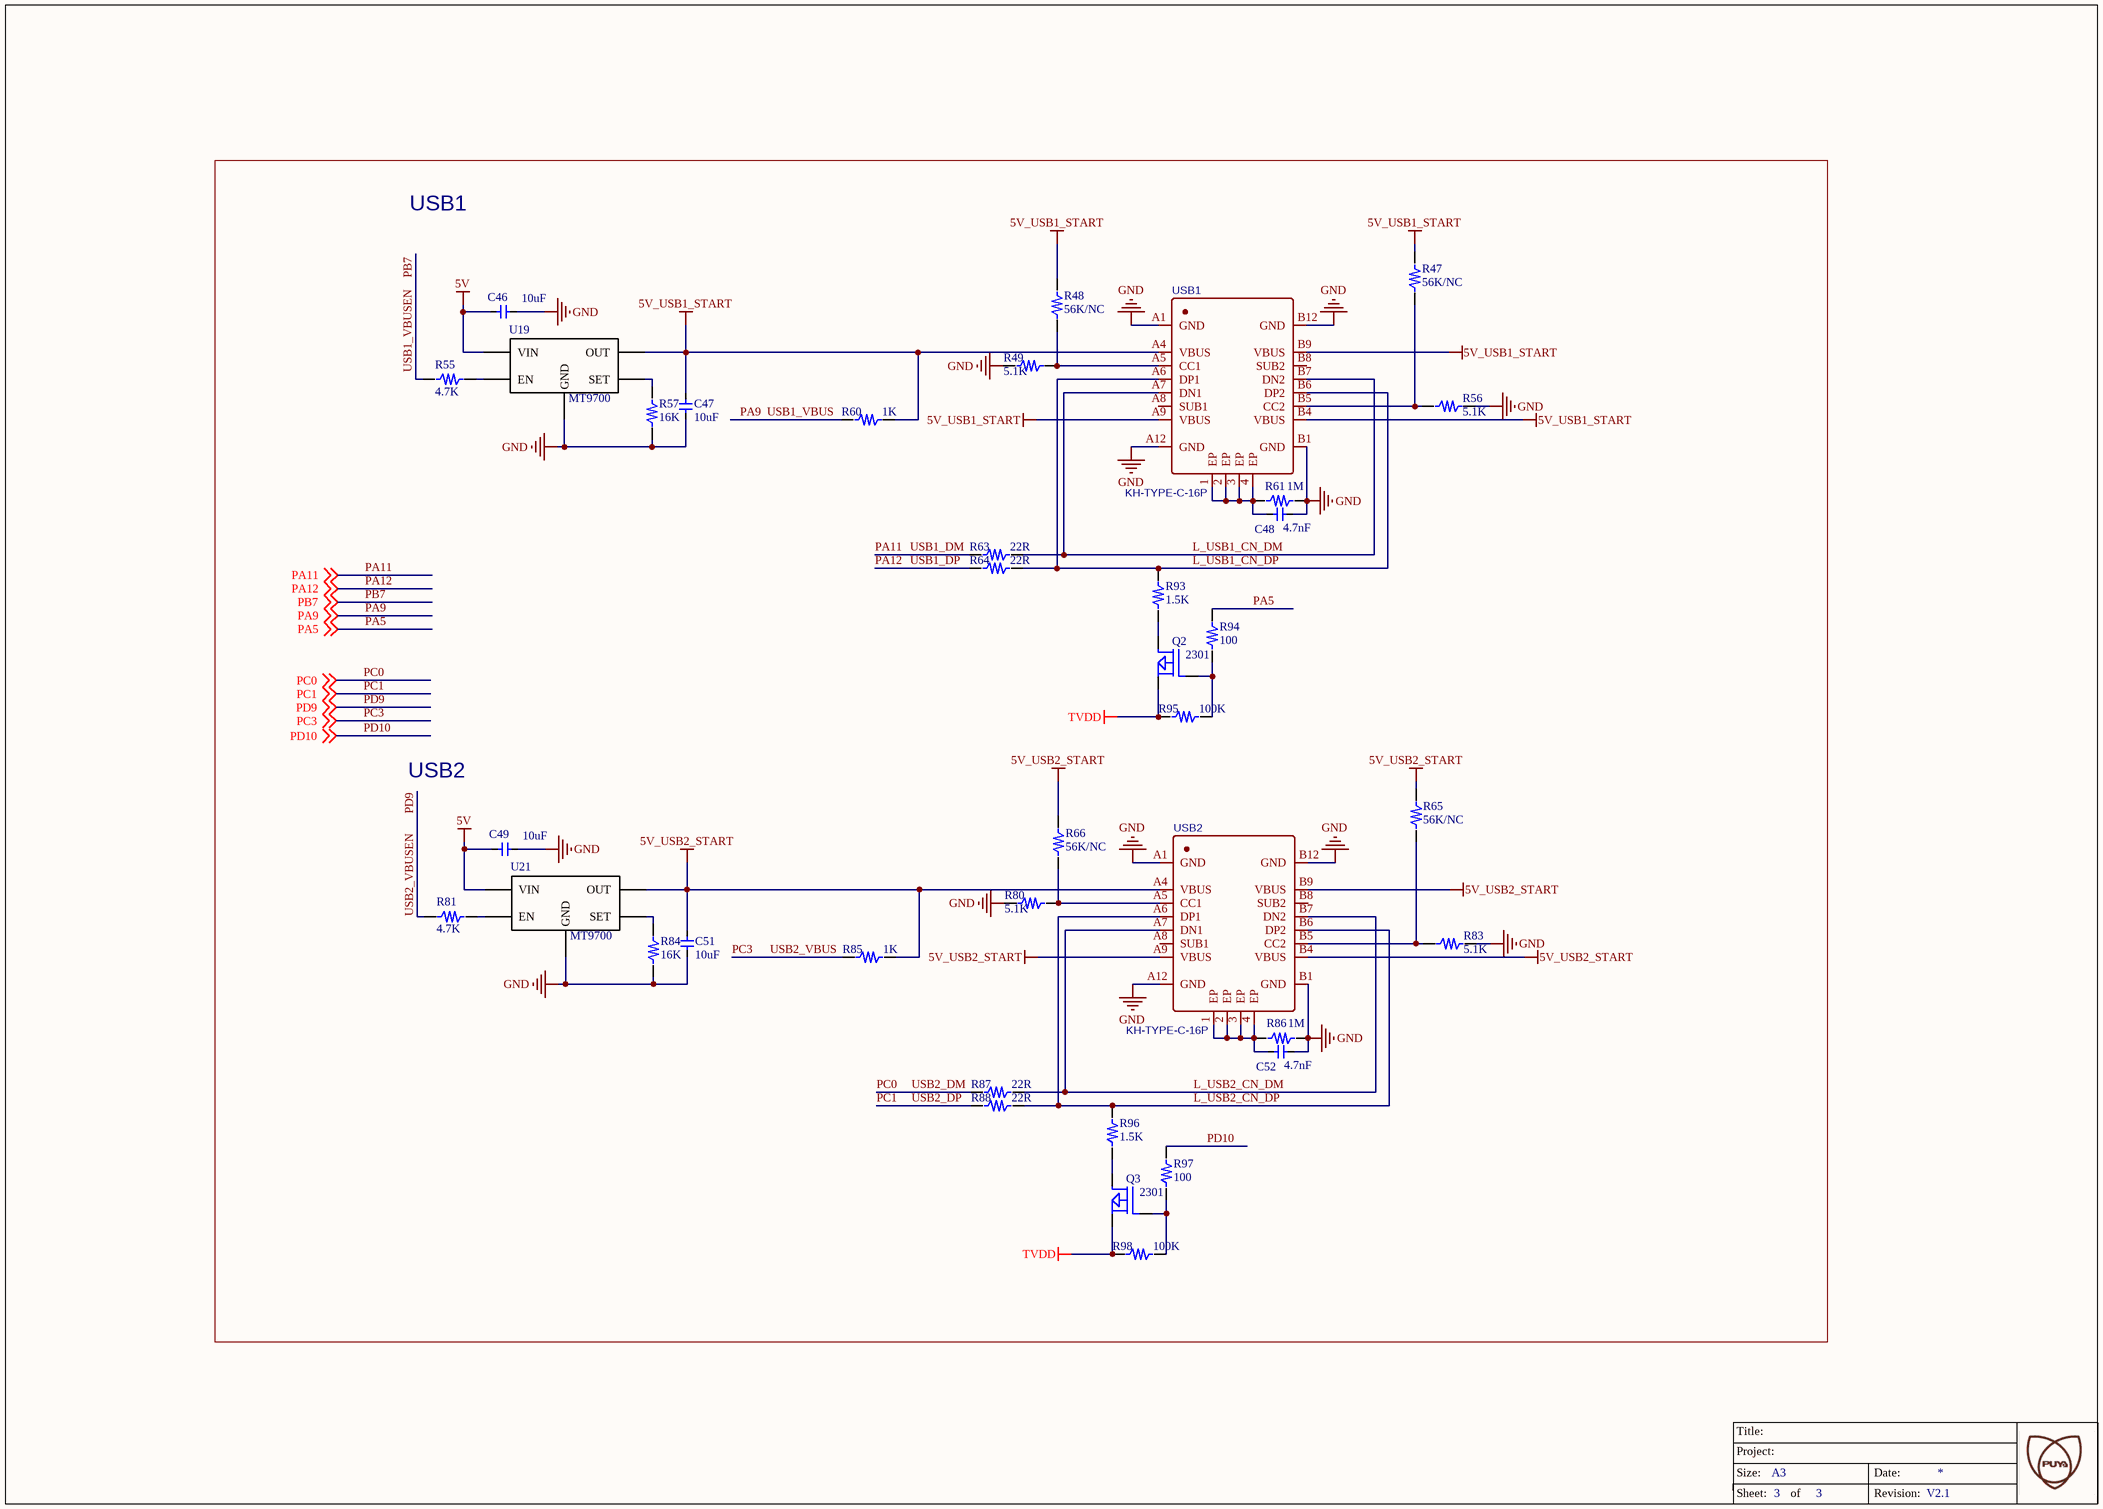
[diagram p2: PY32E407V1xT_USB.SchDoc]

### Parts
C46  10uF  [C0805]
C47  10uF  [C0805]
C48  4.7nF  [C0603]
C49  10uF  [C0805]
C51  10uF  [C0805]
C52  4.7nF  [C0603]
Q2  2301  [SOT23 2301]
Q3  2301  [SOT23 2301]
R47  56K/NC  [R0603]
R48  56K/NC  [R0603]
R49  5.1K  [R0603]
R55  4.7K  [R0603]
R56  5.1K  [R0603]
R57  16K  [R0603]
R60  1K  [R0603]
R61  1M  [R0603]
R63  22R  [R0603]
R64  22R  [R0603]
R65  56K/NC  [R0603]
R66  56K/NC  [R0603]
R80  5.1K  [R0603]
R81  4.7K  [R0603]
R83  5.1K  [R0603]
R84  16K  [R0603]
R85  1K  [R0603]
R86  1M  [R0603]
R87  22R  [R0603]
R88  22R  [R0603]
R93  1.5K  [R0603]
R94  100  [R0603]
R95  100K  [R0603]
R96  1.5K  [R0603]
R97  100  [R0603]
R98  100K  [R0603]
U19  MT9700  [SOT23-5]
U21  MT9700  [SOT23-5]
USB1  KH-TYPE-C-16P  [USB-C-SMD_KH-TYPE-C-16P]
USB2  KH-TYPE-C-16P  [USB-C-SMD_KH-TYPE-C-16P]

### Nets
5V: C46.2 C49.2 U19.5(VIN) U21.5(VIN)
5V_USB1_START: C47.2 R47.2 R48.2 R60.2 U19.1(OUT) USB1.A4(VBUS) USB1.A9(VBUS) USB1.B4(VBUS) USB1.B9(VBUS)
5V_USB2_START: C51.2 R65.2 R66.2 R85.2 U21.1(OUT) USB2.A4(VBUS) USB2.A9(VBUS) USB2.B4(VBUS) USB2.B9(VBUS)
GND: C46.1 C47.1 C48.1 C49.1 C51.1 C52.1 R49.1 R56.2 R57.1 R61.2 R80.1 R83.2 R84.1 R86.2 U19.2(GND) U21.2(GND) USB1.A1(GND) USB1.A12(GND) USB1.B1(GND) USB1.B12(GND) USB2.A1(GND) USB2.A12(GND) USB2.B1(GND) USB2.B12(GND)
TVDD: Q2.2(S) Q3.2(S) R95.1 R98.1
L_USB1_CN_DM: R63.2 USB1.A7(DN1) USB1.B7(DN2)
L_USB1_CN_DP: R64.2 R93.1 USB1.A6(DP1) USB1.B6(DP2)
L_USB2_CN_DM: R87.2 USB2.A7(DN1) USB2.B7(DN2)
L_USB2_CN_DP: R88.2 R96.1 USB2.A6(DP1) USB2.B6(DP2)
PA5: R94.2 ; off-sheet PA5
PA9: R60.1 ; off-sheet PA9  [also labelled USB1_VBUS]
PA11: R63.1 ; off-sheet PA11  [also labelled USB1_DM]
PA12: R64.1 ; off-sheet PA12  [also labelled USB1_DP]
PB7: R55.1 ; off-sheet PB7  [also labelled USB1_VBUSEN]
PC0: R87.1 ; off-sheet PC0  [also labelled USB2_DM]
PC1: R88.1 ; off-sheet PC1  [also labelled USB2_DP]
PC3: R85.1 ; off-sheet PC3  [also labelled USB2_VBUS]
PD9: R81.1 ; off-sheet PD9  [also labelled USB2_VBUSEN]
PD10: R97.2 ; off-sheet PD10
NetC48_2: C48.2 R61.1 USB1.1(EP) USB1.2(EP) USB1.3(EP) USB1.4(EP)
NetC52_2: C52.2 R86.1 USB2.1(EP) USB2.2(EP) USB2.3(EP) USB2.4(EP)
NetQ2_1: Q2.1(G) R94.1 R95.2
NetQ2_3: Q2.3(D) R93.2
NetQ3_1: Q3.1(G) R97.1 R98.2
NetQ3_3: Q3.3(D) R96.2
NetR47_1: R47.1 R56.1 USB1.B5(CC2)
NetR48_1: R48.1 R49.2 USB1.A5(CC1)
NetR55_2: R55.2 U19.4(EN)
NetR57_2: R57.2 U19.3(SET)
NetR65_1: R65.1 R83.1 USB2.B5(CC2)
NetR66_1: R66.1 R80.2 USB2.A5(CC1)
NetR81_2: R81.2 U21.4(EN)
NetR84_2: R84.2 U21.3(SET)

Not connected (* = marked no-connect by the designer): USB1 A8(SUB1) B8(SUB2); USB2 A8(SUB1) B8(SUB2)

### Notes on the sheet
- USB1
- USB2

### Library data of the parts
C46 C47 C49 C51 = C0805: PCB DECAL: 0805
C48 C52 = C0603: PCB DECAL: 0603
Q2 Q3 = MOSFET P: Value: SI2301; 器件封装(外观): SOT23
R47-R49 R55-R57 R60 R61 R63-R66 R80 R81 R83-R88 R93-R98 = R0603: PCB DECAL: 0603
USB1 USB2 = KH-TYPE-C-16P: as PYLK on sheet PY32F403C1xT_LINK

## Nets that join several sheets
5V: PY32E407V1xT_START (D1.1 D2.1 D3.1 F2.1), PY32E407V1xT_USB (C46.2 C49.2 U19.5 U21.5)
5V_USB1_START: PY32E407V1xT_START (JP5.1), PY32E407V1xT_USB (9 pins)
5V_USB2_START: PY32E407V1xT_START (JP6.1), PY32E407V1xT_USB (9 pins)
5V_USB_PYLK: PY32F403C1xT_LINK (C15.2 JP1.3 U16.1), PY32E407V1xT_START (D1.2)
GND: PY32F403C1xT_LINK (65 pins), PY32E407V1xT_START (41 pins), PY32E407V1xT_USB (24 pins)
TVDD: PY32F403C1xT_LINK (17 pins), PY32E407V1xT_START (11 pins), PY32E407V1xT_USB (Q2.2 Q3.2 R95.1 R98.1)
PA5: PY32E407V1xT_START (CN4.27 U18.27), PY32E407V1xT_USB (R94.2)
PA9: PY32E407V1xT_START (CN5.31 U18.70), PY32E407V1xT_USB (R60.1)
PA11: PY32E407V1xT_START (CN5.29 U18.72), PY32E407V1xT_USB (R63.1)
PA12: PY32E407V1xT_START (CN5.28 U18.73), PY32E407V1xT_USB (R64.1)
PB7: PY32E407V1xT_START (CN5.7 U18.94), PY32E407V1xT_USB (R55.1)
PC0: PY32E407V1xT_START (CN4.15 U18.15), PY32E407V1xT_USB (R87.1)
PC1: PY32E407V1xT_START (CN4.16 U18.16), PY32E407V1xT_USB (R88.1)
PC3: PY32E407V1xT_START (CN4.18 U18.18), PY32E407V1xT_USB (R85.1)
PD9: PY32E407V1xT_START (CN5.45 U18.56), PY32E407V1xT_USB (R81.1)
PD10: PY32E407V1xT_START (CN5.44 U18.57), PY32E407V1xT_USB (R97.2)
T_RESET: PY32F403C1xT_LINK (CN1.9 R17.2 U4.4), PY32E407V1xT_START (CN3.5 R39.1)
T_TCK_SWCLK: PY32F403C1xT_LINK (CN1.7 R6.2 U4.5), PY32E407V1xT_START (CN3.4 R38.1)
T_TMS_SWDIO: PY32F403C1xT_LINK (CN1.3 R2.2 R82.2 U4.1), PY32E407V1xT_START (CN3.2 R37.1)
